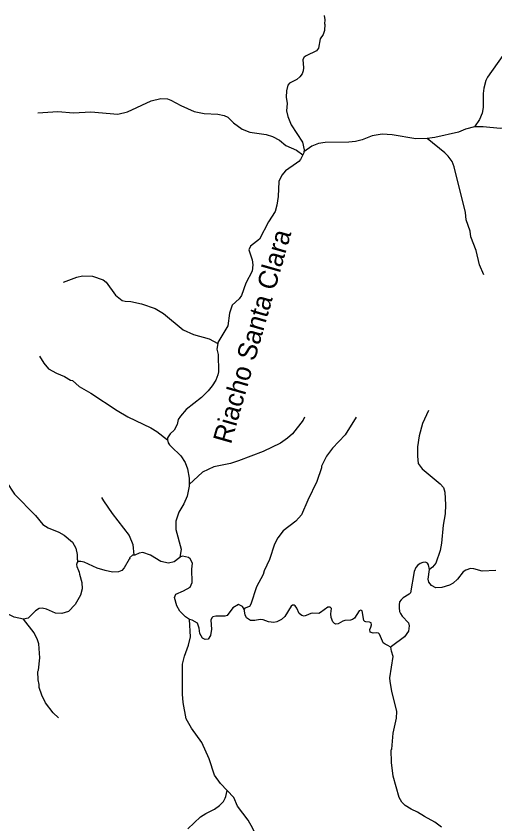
# Model space of a CAD drawing. Extents: x 280.4 to 335.6, y 8893.9 to 8949.5.
# Drawn here: x 316.37 to 321.4, y 8901.25 to 8909.74 of the extents above; entities that cross this region are included whole.
import ezdxf
from ezdxf.enums import TextEntityAlignment as Align

# ---------------------------------------------------------------- set-up
doc = ezdxf.new("R2010")
doc.units = 0
doc.header["$LTSCALE"] = 0.064
doc.layers.add('61', color=7, linetype='Continuous')
doc.layers.add('7', color=7, linetype='Continuous', lineweight=25)

msp = doc.modelspace()

# ---------------------------------------------------------------- linework, layer by layer
at = {"layer": '7'}
for points in [[(321.8219, 8909.8184), (321.7176, 8909.7002), (321.5856, 8909.5113), (321.4877, 8909.3291), (321.3251, 8909.0992), (321.3092, 8909.0653), (321.2855, 8908.9827), (321.2779, 8908.9278), (321.2778, 8908.7808), (321.2699, 8908.7207), (321.241, 8908.6561), (321.1893, 8908.5767)], [(319.6066, 8909.7499), (319.6145, 8909.7031), (319.6088, 8909.6592), (319.6146, 8909.6559), (319.6086, 8909.5915), (319.5954, 8909.549), (319.5652, 8909.5036), (319.5471, 8909.4048), (319.5379, 8909.3904), (319.5263, 8909.3777), (319.4157, 8909.3233), (319.3962, 8909.3102), (319.3829, 8909.2868), (319.3891, 8909.1966), (319.3864, 8909.1649), (319.3744, 8909.1356), (319.3502, 8909.1029), (319.3194, 8909.0764), (319.2409, 8909.0354), (319.2242, 8909.0151), (319.2096, 8908.9552), (319.2084, 8908.8896), (319.2164, 8908.8225), (319.2117, 8908.7455), (319.2228, 8908.6848), (319.2599, 8908.5978), (319.3792, 8908.4168), (319.3954, 8908.3362), (319.3931, 8908.3161)], [(316.5949, 8908.7254), (316.8048, 8908.7376), (316.9694, 8908.7264), (317.1517, 8908.7343), (317.4362, 8908.7123), (317.5387, 8908.735), (317.785, 8908.8527), (317.8882, 8908.8751), (317.957, 8908.8704), (317.9936, 8908.8572), (318.0979, 8908.8003), (318.24, 8908.7405), (318.3448, 8908.7168), (318.4863, 8908.7103), (318.5552, 8908.6977), (318.5916, 8908.6779), (318.6541, 8908.6204), (318.7453, 8908.5541), (318.823, 8908.5205), (318.9949, 8908.4959), (319.0637, 8908.4772), (319.1354, 8908.438), (319.2043, 8908.3806), (319.3139, 8908.3312), (319.3823, 8908.2848)], [(321.1893, 8908.5767), (321.0929, 8908.5524), (321.0187, 8908.5217), (320.7716, 8908.4656), (320.6901, 8908.454)], [(321.9075, 8908.503), (321.7777, 8908.5563), (321.7377, 8908.5632), (321.4569, 8908.5601), (321.281, 8908.576), (321.1893, 8908.5767)], [(320.6901, 8908.454), (320.5725, 8908.4516), (320.3207, 8908.4929), (320.2167, 8908.5008), (320.1103, 8908.4816), (320.0055, 8908.4404), (319.9361, 8908.4244), (319.8648, 8908.4178), (319.6178, 8908.4129), (319.5475, 8908.4017), (319.4771, 8908.3761), (319.3931, 8908.3161)], [(321.2854, 8907.02), (321.2396, 8907.1278), (321.2044, 8907.2763), (321.1486, 8907.4214), (321.1433, 8907.4813), (321.1022, 8907.5999), (321.0937, 8907.678), (320.9759, 8908.1554), (320.9537, 8908.2131), (320.9127, 8908.2693), (320.8764, 8908.3057), (320.6901, 8908.454)], [(319.3823, 8908.2848), (319.3563, 8908.2344), (319.3389, 8908.2127), (319.3162, 8908.1963), (319.2015, 8908.1134), (319.1612, 8908.0691), (319.1304, 8908.0043), (319.1234, 8907.8451), (319.1098, 8907.7537), (319.0912, 8907.6862), (319.0201, 8907.5797), (318.9262, 8907.3954), (318.831, 8907.3246), (318.8153, 8907.2845), (318.8481, 8907.1799), (318.8561, 8907.125)], [(319.3931, 8908.3161), (319.3916, 8908.3029), (319.3823, 8908.2848)], [(318.8561, 8907.125), (318.8486, 8907.0607), (318.7836, 8906.9336), (318.7362, 8906.8034), (318.7122, 8906.7697), (318.6395, 8906.7009), (318.6106, 8906.6169), (318.5922, 8906.4868), (318.4895, 8906.3103), (318.4879, 8906.3003)], [(316.8655, 8906.943), (317.0047, 8906.9975), (317.0628, 8907.0104), (317.1696, 8907.0089), (317.2828, 8906.9688), (317.3122, 8906.9458), (317.4129, 8906.807), (317.4806, 8906.7533), (317.5124, 8906.7436), (317.5723, 8906.7399), (317.6852, 8906.7179), (317.8272, 8906.6693), (317.9161, 8906.6153), (318.1241, 8906.4434), (318.2329, 8906.3956), (318.3984, 8906.35), (318.4879, 8906.3003)], [(318.4879, 8906.3003), (318.4784, 8906.2411), (318.4904, 8906.1851), (318.4951, 8906.002), (318.4884, 8905.9685), (318.4654, 8905.9131), (318.4291, 8905.8535), (318.3858, 8905.8008), (318.3144, 8905.7326), (318.1561, 8905.6046), (318.0941, 8905.5365), (318.0699, 8905.5004), (318.0598, 8905.4472), (318.0285, 8905.3892), (317.985, 8905.3486), (317.9597, 8905.3078), (317.9583, 8905.2849)], [(316.6109, 8906.1668), (316.6588, 8906.0914), (316.7055, 8906.0322), (316.7915, 8905.9862), (316.874, 8905.9528), (316.9369, 8905.9152), (316.9586, 8905.9095), (317.0297, 8905.8481), (317.1501, 8905.7789), (317.4285, 8905.5935), (317.5424, 8905.5285), (317.784, 8905.414), (317.8469, 8905.3746), (317.9583, 8905.2849)], [(320.7043, 8905.5935), (320.6424, 8905.4593), (320.6047, 8905.327), (320.587, 8905.2144), (320.587, 8905.1153), (320.5966, 8905.0392), (320.6385, 8904.9821), (320.8284, 8904.8257), (320.8633, 8904.7855), (320.8766, 8904.7355), (320.8827, 8904.6049), (320.878, 8904.5082), (320.8603, 8904.3909), (320.8426, 8904.199), (320.8281, 8904.1223), (320.7832, 8903.9888), (320.7467, 8903.9462), (320.7148, 8903.9223)], [(319.399, 8905.5238), (319.384, 8905.4945), (319.2725, 8905.3506), (319.2197, 8905.3028), (319.1471, 8905.2509), (318.966, 8905.1651), (318.7047, 8905.0651), (318.6198, 8905.0385), (318.4456, 8905.0012), (318.3283, 8904.9475), (318.186, 8904.8156)], [(319.9428, 8905.5247), (319.8289, 8905.3392), (319.6934, 8905.1974), (319.6299, 8905.1155), (319.5799, 8905.0103), (319.5792, 8904.9908), (319.5299, 8904.8493), (319.4348, 8904.6515), (319.3687, 8904.4969), (319.3102, 8904.4303), (319.1758, 8904.3309), (319.119, 8904.256), (319.0837, 8904.1892), (319.0313, 8904.0291), (318.9748, 8903.9087), (318.9634, 8903.8704), (318.8947, 8903.7407), (318.8343, 8903.5582), (318.8205, 8903.5352), (318.7712, 8903.5171), (318.7635, 8903.5073)], [(317.9583, 8905.2849), (317.9666, 8905.2553), (317.9782, 8905.2352), (317.9972, 8905.2165), (318.0996, 8905.119), (318.1448, 8905.0496), (318.1693, 8904.9823), (318.1848, 8904.8825), (318.186, 8904.8156)], [(315.994, 8905.0002), (316.0004, 8904.9832), (316.0687, 8904.9259), (316.0988, 8904.9124), (316.1953, 8904.8897), (316.2593, 8904.8497), (316.3487, 8904.7142), (316.568, 8904.4915), (316.6468, 8904.3959), (316.7017, 8904.3601), (316.8153, 8904.3157), (316.8702, 8904.2836), (316.9577, 8904.2101), (316.9931, 8904.1468), (317.0078, 8904.0814), (317.0066, 8904.0327), (317.0143, 8904.006)], [(318.186, 8904.8156), (318.1863, 8904.7991), (318.1638, 8904.6955), (318.1317, 8904.6124), (318.0779, 8904.5251), (318.0474, 8904.4307), (318.046, 8904.3438), (318.1031, 8904.1365), (318.0866, 8904.0495)], [(317.2655, 8904.6796), (317.2834, 8904.6447), (317.3773, 8904.5108), (317.5555, 8904.2821), (317.5946, 8904.1875), (317.6029, 8904.0742)], [(317.6029, 8904.0742), (317.5889, 8904.0722), (317.5602, 8904.0451), (317.5607, 8904.0345), (317.5539, 8904.031), (317.503, 8903.939), (317.4794, 8903.9129), (317.4421, 8903.8998), (317.3788, 8903.8967), (317.3016, 8903.9118), (317.2182, 8903.9369), (317.0813, 8904.0004), (317.0461, 8904.0082), (317.0143, 8904.006)], [(318.0866, 8904.0495), (318.0281, 8904.005), (317.969, 8903.9913), (317.8868, 8904.0058), (317.7811, 8904.0744), (317.6986, 8904.1012), (317.6595, 8904.0967), (317.613, 8904.0756), (317.6029, 8904.0742)], [(318.1904, 8903.3961), (318.1483, 8903.4261), (318.089, 8903.4841), (318.0551, 8903.5422), (318.0332, 8903.6279), (318.0456, 8903.6641), (318.1278, 8903.6987), (318.1975, 8903.7387), (318.2188, 8903.788), (318.2136, 8903.9284), (318.22, 8903.9909), (318.1959, 8904.0352), (318.1791, 8904.0502), (318.1153, 8904.063), (318.0939, 8904.055), (318.0866, 8904.0495)], [(317.0143, 8904.006), (317.0092, 8903.9981), (317.0026, 8903.9771), (317.0041, 8903.9563), (317.0205, 8903.9134), (317.028, 8903.8961), (317.034, 8903.8751), (317.0574, 8903.7861), (317.0589, 8903.7183), (317.0417, 8903.6519), (316.9854, 8903.5544), (316.9179, 8903.4821), (316.8475, 8903.4591), (316.78, 8903.4651), (316.6845, 8903.5068), (316.6399, 8903.5158), (316.6065, 8903.5129), (316.5702, 8903.4893), (316.4927, 8903.4107), (316.4437, 8903.4019)], [(320.7148, 8903.9223), (320.7046, 8903.9724), (320.693, 8903.9901), (320.6738, 8904.0007), (320.6445, 8903.9981), (320.6181, 8903.9879), (320.5938, 8903.9701), (320.5708, 8903.9451), (320.5552, 8903.9006), (320.5166, 8903.6782), (320.5006, 8903.6622), (320.4368, 8903.6262), (320.4169, 8903.6059), (320.4002, 8903.583), (320.3963, 8903.5506), (320.3951, 8903.5209), (320.4, 8903.4815), (320.4105, 8903.4606), (320.4264, 8903.4342), (320.494, 8903.3639), (320.5004, 8903.3304), (320.4956, 8903.2746), (320.453, 8903.2143), (320.3165, 8903.1142), (320.3069, 8903.1066)], [(321.4121, 8903.9126), (321.269, 8903.9062), (321.1818, 8903.9301), (321.1465, 8903.9335), (321.0964, 8903.9161), (321.0699, 8903.8982), (321.008, 8903.8218), (320.9631, 8903.7778), (320.9253, 8903.7588), (320.8439, 8903.733), (320.7821, 8903.7304), (320.7363, 8903.7539), (320.7069, 8903.7886), (320.7007, 8903.8214), (320.7148, 8903.9223)], [(316.4437, 8903.4019), (316.3449, 8903.4218), (316.0842, 8903.5511), (316.0379, 8903.5559), (315.8987, 8903.5416), (315.7579, 8903.5416)], [(318.7635, 8903.5073), (318.7487, 8903.5339), (318.7037, 8903.5538), (318.6451, 8903.5199), (318.587, 8903.4392), (318.5606, 8903.4313), (318.4656, 8903.4341), (318.4353, 8903.425), (318.4234, 8903.4149), (318.4152, 8903.3905), (318.4214, 8903.2946), (318.4106, 8903.2298), (318.3848, 8903.1903), (318.3537, 8903.1855), (318.327, 8903.2017), (318.299, 8903.2501), (318.2921, 8903.3073), (318.2737, 8903.3596), (318.2186, 8903.392), (318.1904, 8903.3961)], [(319.716, 8903.3557), (319.6991, 8903.3731), (319.6798, 8903.4181), (319.6773, 8903.4579), (319.6849, 8903.5148), (319.6712, 8903.5283), (319.6442, 8903.5274), (319.5692, 8903.4696), (319.5513, 8903.4621), (319.4842, 8903.4631), (319.465, 8903.46), (319.4186, 8903.4413), (319.395, 8903.433), (319.3723, 8903.4387), (319.3453, 8903.4612), (319.3186, 8903.516), (319.3029, 8903.5416), (319.2898, 8903.5491), (319.2733, 8903.5493), (319.2596, 8903.5366), (319.1928, 8903.4303), (319.158, 8903.3968), (319.1075, 8903.3727), (319.0757, 8903.3658), (319.0212, 8903.3734), (318.9637, 8903.3939), (318.934, 8903.3975), (318.8757, 8903.3881), (318.8313, 8903.3887), (318.7907, 8903.4145), (318.7766, 8903.4457), (318.7635, 8903.5073)], [(320.3069, 8903.1066), (320.269, 8903.1261), (320.2471, 8903.1377), (320.2289, 8903.1532), (320.2188, 8903.1711), (320.1995, 8903.22), (320.1905, 8903.2419), (320.1777, 8903.2531), (320.1596, 8903.2573), (320.1239, 8903.2539), (320.0914, 8903.2654), (320.0866, 8903.2921), (320.096, 8903.3184), (320.1043, 8903.3422), (320.0995, 8903.361), (320.0824, 8903.3692), (320.0459, 8903.3741), (320.0348, 8903.3769), (320.0244, 8903.3883), (320.0076, 8903.4881), (319.991, 8903.4973), (319.9741, 8903.4883), (319.9254, 8903.4131), (319.9049, 8903.3975), (319.8832, 8903.3914), (319.825, 8903.3877), (319.8046, 8903.3795), (319.7544, 8903.3525), (319.7309, 8903.3481), (319.716, 8903.3557)], [(316.8102, 8902.3633), (316.7564, 8902.416), (316.6752, 8902.5213), (316.6359, 8902.6006), (316.6093, 8902.6826), (316.6094, 8902.7124), (316.5985, 8902.7636), (316.5938, 8902.8499), (316.6002, 8902.8656), (316.6143, 8902.9947), (316.6044, 8903.1401), (316.5859, 8903.1954), (316.5572, 8903.2531), (316.5551, 8903.2558), (316.4437, 8903.4019)], [(318.5867, 8901.5987), (318.5174, 8901.6731), (318.4515, 8901.7616), (318.3973, 8901.9334), (318.3179, 8902.1048), (318.21, 8902.2564), (318.154, 8902.3533), (318.1243, 8902.5238), (318.1161, 8902.6116), (318.1178, 8902.9267), (318.1362, 8903.0111), (318.1781, 8903.1283), (318.2005, 8903.2138), (318.1904, 8903.3961)], [(320.8408, 8901.215), (320.7708, 8901.2648), (320.6636, 8901.3274), (320.588, 8901.3716), (320.5204, 8901.4015), (320.4575, 8901.4419), (320.4249, 8901.478), (320.397, 8901.526), (320.3328, 8901.7498), (320.3151, 8901.895), (320.3119, 8902.0262), (320.3182, 8902.0351), (320.3327, 8902.2039), (320.3678, 8902.3613), (320.3726, 8902.431), (320.3181, 8902.6436), (320.2994, 8902.7453), (320.2991, 8902.7835), (320.331, 8903.01), (320.3136, 8903.0643), (320.3069, 8903.1066)], [(318.1713, 8901.1968), (318.3062, 8901.3228), (318.3608, 8901.3585), (318.4519, 8901.4018), (318.505, 8901.4407), (318.5467, 8901.4846), (318.5662, 8901.5186), (318.571, 8901.5375), (318.5867, 8901.5987)], [(318.8055, 8900.7094), (318.8063, 8900.7193), (318.8088, 8900.7501), (318.8224, 8900.7832), (318.8433, 8900.8126), (318.914, 8900.8845), (318.9268, 8900.9396), (318.9237, 8901.0268), (318.9113, 8901.0835), (318.8562, 8901.2009), (318.8053, 8901.2866), (318.6961, 8901.4355), (318.6556, 8901.5247), (318.5867, 8901.5987)]]:
    msp.add_lwpolyline(points, dxfattribs=at)

# ---------------------------------------------------------------- texts
at = {"layer": '61'}
msp.add_text('Riacho Santa Clara', height=0.2, rotation=74.055, dxfattribs=at).set_placement((318.9441, 8906.3481), align=Align.CENTER)

doc.saveas('drawing.dxf')
